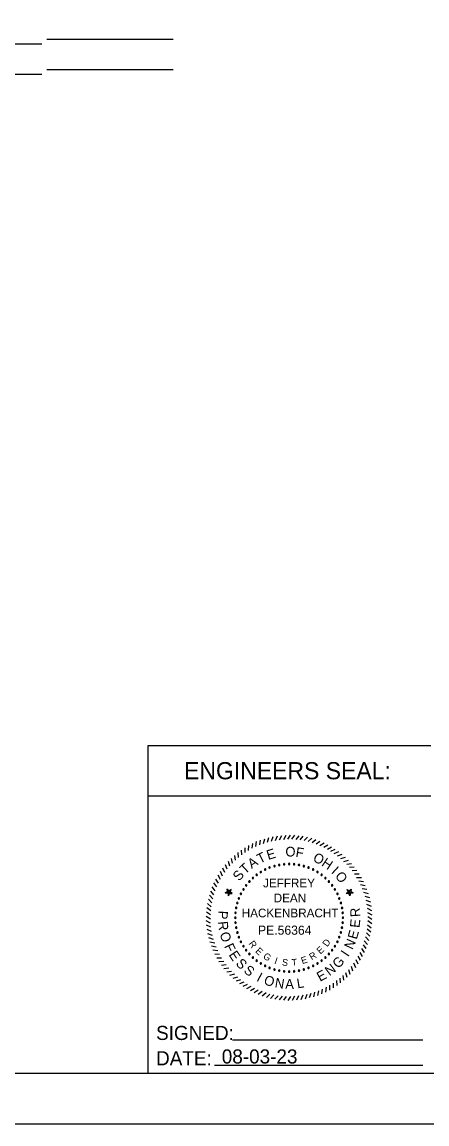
# Model space of a CAD drawing. Extents: x 0 to 34, y 0 to 22.
# Drawn here: x 8 to 12.01, y 0 to 10.92 of the extents above; entities that cross this region are included whole.
import ezdxf

# ---------------------------------------------------------------- set-up
doc = ezdxf.new("R2010")
doc.units = 0
for name, color, linetype in [('SH_Border', 7, 'Continuous'), ('SH_Cut_Line', 7, 'Continuous'), ('SH_Data', 7, 'Continuous'), ('SH_Text', 7, 'Continuous')]:
    doc.layers.add(name, color=color, linetype=linetype)

msp = doc.modelspace()

# ---------------------------------------------------------------- linework, layer by layer
at = {"layer": 'SH_Border'}
msp.add_lwpolyline([(2, 21.5), (33.5, 21.5), (33.5, 0.5), (2, 0.5)], close=True, dxfattribs=at)
at = {"layer": 'SH_Cut_Line'}
msp.add_lwpolyline([(0, 0), (34, 0), (34, 22), (0, 22)], close=True, dxfattribs=at)
at = {"layer": 'SH_Data'}
for p, q in [((9.5, 10.743), (8.25, 10.743)), ((8.2, 10.697), (5.424, 10.697)), ((8.2, 10.397), (3.935, 10.397)), ((9.5, 10.443), (8.25, 10.443)), ((9.25, 0.5), (9.25, 3.75)), ((9.25, 3.75), (12.05, 3.75)), ((9.25, 3.25), (12.05, 3.25)), ((10.086, 0.832), (11.971, 0.832)), ((9.908, 0.581), (11.971, 0.581))]:
    msp.add_line(p, q, dxfattribs=at)
at = {"layer": 'SH_Text'}
for p, q in [((10.472, 2.802), (10.489, 2.847)), ((10.512, 2.81), (10.531, 2.854)), ((10.552, 2.816), (10.574, 2.859)), ((10.593, 2.82), (10.616, 2.862)), ((10.634, 2.822), (10.659, 2.862)), ((10.675, 2.821), (10.702, 2.86)), ((10.715, 2.819), (10.745, 2.856)), ((10.756, 2.814), (10.787, 2.85)), ((10.796, 2.807), (10.829, 2.842)), ((10.212, 2.689), (10.211, 2.737)), ((10.246, 2.711), (10.248, 2.759)), ((10.282, 2.731), (10.286, 2.779)), ((10.318, 2.749), (10.325, 2.797)), ((10.356, 2.765), (10.365, 2.812)), ((10.394, 2.78), (10.405, 2.826)), ((10.433, 2.792), (10.447, 2.838)), ((10.836, 2.798), (10.871, 2.831)), ((10.875, 2.787), (10.912, 2.818)), ((10.914, 2.774), (10.952, 2.803)), ((10.952, 2.759), (10.992, 2.786)), ((10.989, 2.742), (11.03, 2.767)), ((11.025, 2.724), (11.067, 2.746)), ((10.087, 2.584), (10.076, 2.631)), ((10.116, 2.613), (10.108, 2.66)), ((10.146, 2.64), (10.141, 2.688)), ((10.178, 2.665), (10.175, 2.713)), ((11.06, 2.703), (11.104, 2.723)), ((11.094, 2.68), (11.139, 2.698)), ((11.127, 2.656), (11.172, 2.672)), ((11.158, 2.63), (11.204, 2.643)), ((10.009, 2.49), (9.991, 2.535)), ((10.033, 2.523), (10.018, 2.568)), ((10.059, 2.554), (10.046, 2.601)), ((11.188, 2.602), (11.235, 2.613)), ((11.217, 2.573), (11.264, 2.582)), ((11.244, 2.543), (11.291, 2.549)), ((11.269, 2.511), (11.317, 2.514)), ((9.947, 2.385), (9.922, 2.426)), ((9.966, 2.421), (9.943, 2.464)), ((9.986, 2.456), (9.966, 2.5)), ((11.293, 2.478), (11.341, 2.478)), ((11.315, 2.443), (11.363, 2.441)), ((11.335, 2.408), (11.383, 2.403)), ((9.902, 2.271), (9.871, 2.308)), ((9.915, 2.31), (9.886, 2.348)), ((9.93, 2.348), (9.903, 2.388)), ((10.037, 2.302), (10.015, 2.289)), ((10.051, 2.31), (10.031, 2.327)), ((10.031, 2.327), (10.037, 2.302)), ((10.073, 2.323), (10.051, 2.31)), ((10.063, 2.3), (10.073, 2.323)), ((10.082, 2.282), (10.063, 2.3)), ((11.211, 2.282), (11.23, 2.3)), ((11.22, 2.323), (11.242, 2.31)), ((11.23, 2.3), (11.22, 2.323)), ((11.242, 2.31), (11.262, 2.327)), ((11.262, 2.327), (11.256, 2.302)), ((11.256, 2.302), (11.279, 2.289)), ((11.353, 2.371), (11.4, 2.364)), ((11.369, 2.334), (11.416, 2.325)), ((11.383, 2.296), (11.43, 2.284)), ((9.875, 2.152), (9.839, 2.184)), ((9.882, 2.192), (9.848, 2.226)), ((9.891, 2.232), (9.858, 2.267)), ((10.015, 2.289), (10.04, 2.286)), ((10.04, 2.286), (10.046, 2.261)), ((10.046, 2.261), (10.056, 2.285)), ((10.056, 2.285), (10.082, 2.282)), ((11.237, 2.285), (11.211, 2.282)), ((11.247, 2.261), (11.237, 2.285)), ((11.253, 2.286), (11.247, 2.261)), ((11.279, 2.289), (11.253, 2.286)), ((11.396, 2.257), (11.441, 2.243)), ((11.406, 2.217), (11.451, 2.201)), ((9.868, 2.071), (9.829, 2.098)), ((9.871, 2.111), (9.833, 2.141)), ((11.414, 2.177), (11.458, 2.158)), ((11.42, 2.137), (11.463, 2.116)), ((11.424, 2.096), (11.466, 2.073)), ((9.868, 2.03), (9.827, 2.055)), ((9.869, 1.989), (9.827, 2.013)), ((9.873, 1.949), (9.83, 1.97)), ((11.422, 1.974), (11.46, 1.944)), ((11.425, 2.055), (11.466, 2.03)), ((11.425, 2.015), (11.464, 1.987)), ((9.879, 1.908), (9.835, 1.927)), ((9.887, 1.868), (9.842, 1.885)), ((11.411, 1.893), (11.446, 1.86)), ((11.418, 1.933), (11.454, 1.902)), ((9.898, 1.829), (9.852, 1.843)), ((9.91, 1.79), (9.863, 1.802)), ((9.924, 1.752), (9.877, 1.761)), ((11.378, 1.776), (11.407, 1.737)), ((11.391, 1.814), (11.422, 1.777)), ((11.402, 1.853), (11.435, 1.818)), ((9.94, 1.714), (9.893, 1.721)), ((9.958, 1.678), (9.911, 1.682)), ((9.978, 1.642), (9.93, 1.644)), ((11.327, 1.664), (11.35, 1.622)), ((11.346, 1.7), (11.371, 1.659)), ((11.363, 1.738), (11.39, 1.698)), ((10, 1.608), (9.952, 1.607)), ((10.024, 1.575), (9.976, 1.571)), ((10.049, 1.543), (10.002, 1.537)), ((11.234, 1.531), (11.247, 1.485)), ((11.26, 1.562), (11.275, 1.517)), ((11.284, 1.595), (11.302, 1.551)), ((11.307, 1.629), (11.327, 1.586)), ((10.076, 1.512), (10.029, 1.504)), ((10.105, 1.483), (10.058, 1.472)), ((10.135, 1.455), (10.089, 1.442)), ((10.166, 1.429), (10.121, 1.414)), ((11.115, 1.42), (11.118, 1.372)), ((11.147, 1.445), (11.152, 1.398)), ((11.177, 1.472), (11.185, 1.425)), ((11.206, 1.501), (11.217, 1.454)), ((10.199, 1.405), (10.155, 1.387)), ((10.233, 1.383), (10.19, 1.362)), ((10.268, 1.362), (10.226, 1.339)), ((10.304, 1.343), (10.263, 1.318)), ((10.341, 1.326), (10.302, 1.299)), ((10.379, 1.311), (10.341, 1.282)), ((10.938, 1.32), (10.928, 1.273)), ((10.975, 1.336), (10.968, 1.289)), ((11.012, 1.355), (11.007, 1.307)), ((11.047, 1.375), (11.045, 1.327)), ((11.081, 1.396), (11.082, 1.348)), ((10.418, 1.298), (10.381, 1.267)), ((10.457, 1.287), (10.422, 1.254)), ((10.497, 1.278), (10.464, 1.244)), ((10.537, 1.271), (10.506, 1.235)), ((10.578, 1.267), (10.548, 1.229)), ((10.619, 1.264), (10.591, 1.225)), ((10.659, 1.264), (10.634, 1.223)), ((10.7, 1.266), (10.677, 1.224)), ((10.741, 1.269), (10.72, 1.226)), ((10.781, 1.275), (10.762, 1.231)), ((10.821, 1.284), (10.804, 1.238)), ((10.86, 1.294), (10.846, 1.248)), ((10.899, 1.306), (10.888, 1.259))]:
    msp.add_line(p, q, dxfattribs=at)
for points in [[(10.015, 2.289), (10.037, 2.302), (10.04, 2.286)], [(10.031, 2.327), (10.046, 2.261), (10.051, 2.31)], [(10.073, 2.323), (10.051, 2.31), (10.046, 2.261)], [(10.082, 2.282), (10.063, 2.3), (10.056, 2.285)], [(11.211, 2.282), (11.23, 2.3), (11.237, 2.285)], [(11.22, 2.323), (11.242, 2.31), (11.247, 2.261)], [(11.262, 2.327), (11.247, 2.261), (11.242, 2.31)], [(11.279, 2.289), (11.256, 2.302), (11.253, 2.286)]]:
    msp.add_lwpolyline(points, close=True, dxfattribs=at)
for centre, start, end in [((10.409, 2.52), 26.4706, 206.4706), ((10.409, 2.52), 206.4706, 26.4706), ((10.454, 2.54), 21.1765, 201.1765), ((10.454, 2.54), 201.1765, 21.1765), ((10.501, 2.555), 15.8824, 195.8824), ((10.501, 2.555), 195.8824, 15.8824), ((10.549, 2.566), 10.5882, 190.5882), ((10.549, 2.566), 190.5882, 10.5882), ((10.597, 2.573), 5.2941, 185.2941), ((10.597, 2.573), 185.2941, 5.2941), ((10.647, 2.576), 0, 180), ((10.647, 2.576), 180, 0), ((10.696, 2.573), 354.7059, 174.7059), ((10.696, 2.573), 174.7059, 354.7059), ((10.744, 2.566), 349.4118, 169.4118), ((10.744, 2.566), 169.4118, 349.4118), ((10.792, 2.555), 344.1176, 164.1176), ((10.792, 2.555), 164.1176, 344.1176), ((10.839, 2.54), 338.8235, 158.8235), ((10.839, 2.54), 158.8235, 338.8235), ((10.884, 2.52), 153.5294, 333.5294), ((10.884, 2.52), 333.5294, 153.5294), ((10.253, 2.402), 47.6471, 227.6471), ((10.253, 2.402), 227.6471, 47.6471), ((10.288, 2.436), 42.3529, 222.3529), ((10.288, 2.436), 222.3529, 42.3529), ((10.325, 2.468), 37.0588, 217.0588), ((10.325, 2.468), 217.0588, 37.0588), ((10.366, 2.496), 31.7647, 211.7647), ((10.366, 2.496), 211.7647, 31.7647), ((10.927, 2.496), 148.2353, 328.2353), ((10.927, 2.496), 328.2353, 148.2353), ((10.968, 2.468), 142.9412, 322.9412), ((10.968, 2.468), 322.9412, 142.9412), ((11.006, 2.436), 137.6471, 317.6471), ((11.006, 2.436), 317.6471, 137.6471), ((11.04, 2.402), 132.3529, 312.3529), ((11.04, 2.402), 312.3529, 132.3529), ((10.194, 2.323), 58.2353, 238.2353), ((10.194, 2.323), 238.2353, 58.2353), ((10.221, 2.364), 52.9412, 232.9412), ((10.221, 2.364), 232.9412, 52.9412), ((11.072, 2.364), 127.0588, 307.0588), ((11.072, 2.364), 307.0588, 127.0588), ((11.1, 2.323), 121.7647, 301.7647), ((11.1, 2.323), 301.7647, 121.7647), ((10.134, 2.189), 74.1176, 254.1176), ((10.134, 2.189), 254.1176, 74.1176), ((10.15, 2.235), 68.8235, 248.8235), ((10.15, 2.235), 248.8235, 68.8235), ((10.17, 2.28), 63.5294, 243.5294), ((10.17, 2.28), 243.5294, 63.5294), ((11.124, 2.28), 116.4706, 296.4706), ((11.124, 2.28), 296.4706, 116.4706), ((11.143, 2.235), 111.1765, 291.1765), ((11.143, 2.235), 291.1765, 111.1765), ((11.159, 2.189), 105.8824, 285.8824), ((11.159, 2.189), 285.8824, 105.8824), ((10.116, 2.092), 84.7059, 264.7059), ((10.116, 2.092), 264.7059, 84.7059), ((10.123, 2.141), 79.4118, 259.4118), ((10.123, 2.141), 259.4118, 79.4118), ((11.17, 2.141), 100.5882, 280.5882), ((11.17, 2.141), 280.5882, 100.5882), ((11.177, 2.092), 95.2941, 275.2941), ((11.177, 2.092), 275.2941, 95.2941), ((10.114, 2.043), 90, 270), ((10.116, 1.994), 95.2941, 275.2941), ((10.114, 2.043), 270, 90), ((10.116, 1.994), 275.2941, 95.2941), ((11.177, 1.994), 84.7059, 264.7059), ((11.179, 2.043), 90, 270), ((11.177, 1.994), 264.7059, 84.7059), ((11.179, 2.043), 270, 90), ((10.123, 1.945), 100.5882, 280.5882), ((10.123, 1.945), 280.5882, 100.5882), ((10.134, 1.897), 105.8824, 285.8824), ((10.134, 1.897), 285.8824, 105.8824), ((10.15, 1.85), 111.1765, 291.1765), ((10.15, 1.85), 291.1765, 111.1765), ((11.143, 1.85), 68.8235, 248.8235), ((11.143, 1.85), 248.8235, 68.8235), ((11.159, 1.897), 74.1176, 254.1176), ((11.159, 1.897), 254.1176, 74.1176), ((11.17, 1.945), 79.4118, 259.4118), ((11.17, 1.945), 259.4118, 79.4118), ((10.17, 1.805), 116.4706, 296.4706), ((10.17, 1.805), 296.4706, 116.4706), ((10.194, 1.762), 121.7647, 301.7647), ((10.194, 1.762), 301.7647, 121.7647), ((11.1, 1.762), 58.2353, 238.2353), ((11.1, 1.762), 238.2353, 58.2353), ((11.124, 1.805), 63.5294, 243.5294), ((11.124, 1.805), 243.5294, 63.5294), ((10.221, 1.722), 127.0588, 307.0588), ((10.221, 1.722), 307.0588, 127.0588), ((10.253, 1.684), 132.3529, 312.3529), ((10.253, 1.684), 312.3529, 132.3529), ((10.288, 1.649), 137.6471, 317.6471), ((10.288, 1.649), 317.6471, 137.6471), ((11.006, 1.649), 42.3529, 222.3529), ((11.006, 1.649), 222.3529, 42.3529), ((11.04, 1.684), 47.6471, 227.6471), ((11.04, 1.684), 227.6471, 47.6471), ((11.072, 1.722), 52.9412, 232.9412), ((11.072, 1.722), 232.9412, 52.9412), ((10.325, 1.618), 142.9412, 322.9412), ((10.325, 1.618), 322.9412, 142.9412), ((10.366, 1.59), 148.2353, 328.2353), ((10.366, 1.59), 328.2353, 148.2353), ((10.409, 1.566), 153.5294, 333.5294), ((10.409, 1.566), 333.5294, 153.5294), ((10.454, 1.546), 338.8235, 158.8235), ((10.454, 1.546), 158.8235, 338.8235), ((10.501, 1.53), 344.1176, 164.1176), ((10.501, 1.53), 164.1176, 344.1176), ((10.792, 1.53), 15.8824, 195.8824), ((10.792, 1.53), 195.8824, 15.8824), ((10.839, 1.546), 21.1765, 201.1765), ((10.839, 1.546), 201.1765, 21.1765), ((10.884, 1.566), 26.4706, 206.4706), ((10.884, 1.566), 206.4706, 26.4706), ((10.927, 1.59), 31.7647, 211.7647), ((10.927, 1.59), 211.7647, 31.7647), ((10.968, 1.618), 37.0588, 217.0588), ((10.968, 1.618), 217.0588, 37.0588), ((10.549, 1.519), 169.4118, 349.4118), ((10.549, 1.519), 349.4118, 169.4118), ((10.597, 1.512), 354.7059, 174.7059), ((10.597, 1.512), 174.7059, 354.7059), ((10.647, 1.51), 0, 180), ((10.647, 1.51), 180, 0), ((10.696, 1.512), 5.2941, 185.2941), ((10.696, 1.512), 185.2941, 5.2941), ((10.744, 1.519), 10.5882, 190.5882), ((10.744, 1.519), 190.5882, 10.5882)]:
    msp.add_arc(centre, 0.0072, start, end, dxfattribs=at)

# ---------------------------------------------------------------- texts
at = {"layer": 'SH_Data'}
for s, height, p in [('ENGINEERS SEAL:', 0.17, (9.607, 3.415)), ('SIGNED:', 0.14, (9.33, 0.832)), ('DATE:', 0.14, (9.33, 0.581)), ('08-03-23', 0.14, (9.98, 0.599))]:
    msp.add_text(s, height=height, dxfattribs=at).set_placement(p)
at = {"layer": 'SH_Text'}
for s, height, rotation, p in [('E', 0.096, 17, (10.44, 2.615)), ('F', 0.096, 351.5, (10.707, 2.648)), ('A', 0.096, 34, (10.276, 2.526)), ('T', 0.096, 25.5, (10.356, 2.577)), ('O', 0.096, 334.5, (10.875, 2.607)), ('H', 0.096, 326, (10.96, 2.564)), ('S', 0.096, 51, (10.154, 2.4)), ('T', 0.096, 42.5, (10.212, 2.469)), ('I', 0.096, 317.5, (11.057, 2.491)), ('O', 0.096, 309, (11.096, 2.454)), ('P', 0.096, 266.75, (9.946, 2.115)), ('R', 0.096, 93.4067, (11.351, 2.053)), ('R', 0.096, 275.7323, (9.943, 2.004)), ('E', 0.096, 84.054, (11.343, 1.94)), ('O', 0.096, 285.6791, (9.959, 1.888)), ('E', 0.096, 74.2625, (11.316, 1.823)), ('F', 0.096, 296.025, (10.001, 1.761)), ('R', 0.0672, 305, (10.242, 1.787)), ('E', 0.0672, 317.2222, (10.307, 1.706)), ('E', 0.0672, 42.7778, (10.956, 1.678)), ('D', 0.0672, 55, (11.025, 1.75)), ('N', 0.096, 65.4585, (11.273, 1.721)), ('E', 0.096, 303.7619, (10.045, 1.676)), ('G', 0.0672, 329.4444, (10.383, 1.644)), ('I', 0.0672, 341.6667, (10.496, 1.589)), ('T', 0.0672, 6.1111, (10.675, 1.565)), ('E', 0.0672, 18.3333, (10.777, 1.583)), ('R', 0.0672, 30.5556, (10.87, 1.62)), ('G', 0.096, 46.6014, (11.134, 1.534)), ('I', 0.096, 55.9965, (11.23, 1.649)), ('S', 0.096, 313.1839, (10.112, 1.585)), ('S', 0.096, 322.1523, (10.19, 1.507)), ('S', 0.0672, 353.8889, (10.573, 1.57)), ('E', 0.096, 28.1233, (10.952, 1.408)), ('N', 0.096, 37.1648, (11.046, 1.463)), ('I', 0.096, 332.0387, (10.317, 1.421)), ('O', 0.096, 341.4958, (10.389, 1.387)), ('N', 0.096, 350.5588, (10.5, 1.354)), ('A', 0.096, 359.8179, (10.608, 1.339)), ('L', 0.096, 9.0114, (10.73, 1.343))]:
    msp.add_text(s, height=height, rotation=rotation, dxfattribs=at).set_placement(p)
for s, height, p in [('O', 0.096, (10.61, 2.65)), ('JEFFREY', 0.0864, (10.389, 2.344)), ('DEAN', 0.0864, (10.494, 2.196)), ('HACKENBRACHT', 0.0864, (10.178, 2.047)), ('PE.56364', 0.09, (10.339, 1.875))]:
    msp.add_text(s, height=height, dxfattribs=at).set_placement(p)

doc.saveas('drawing.dxf')
